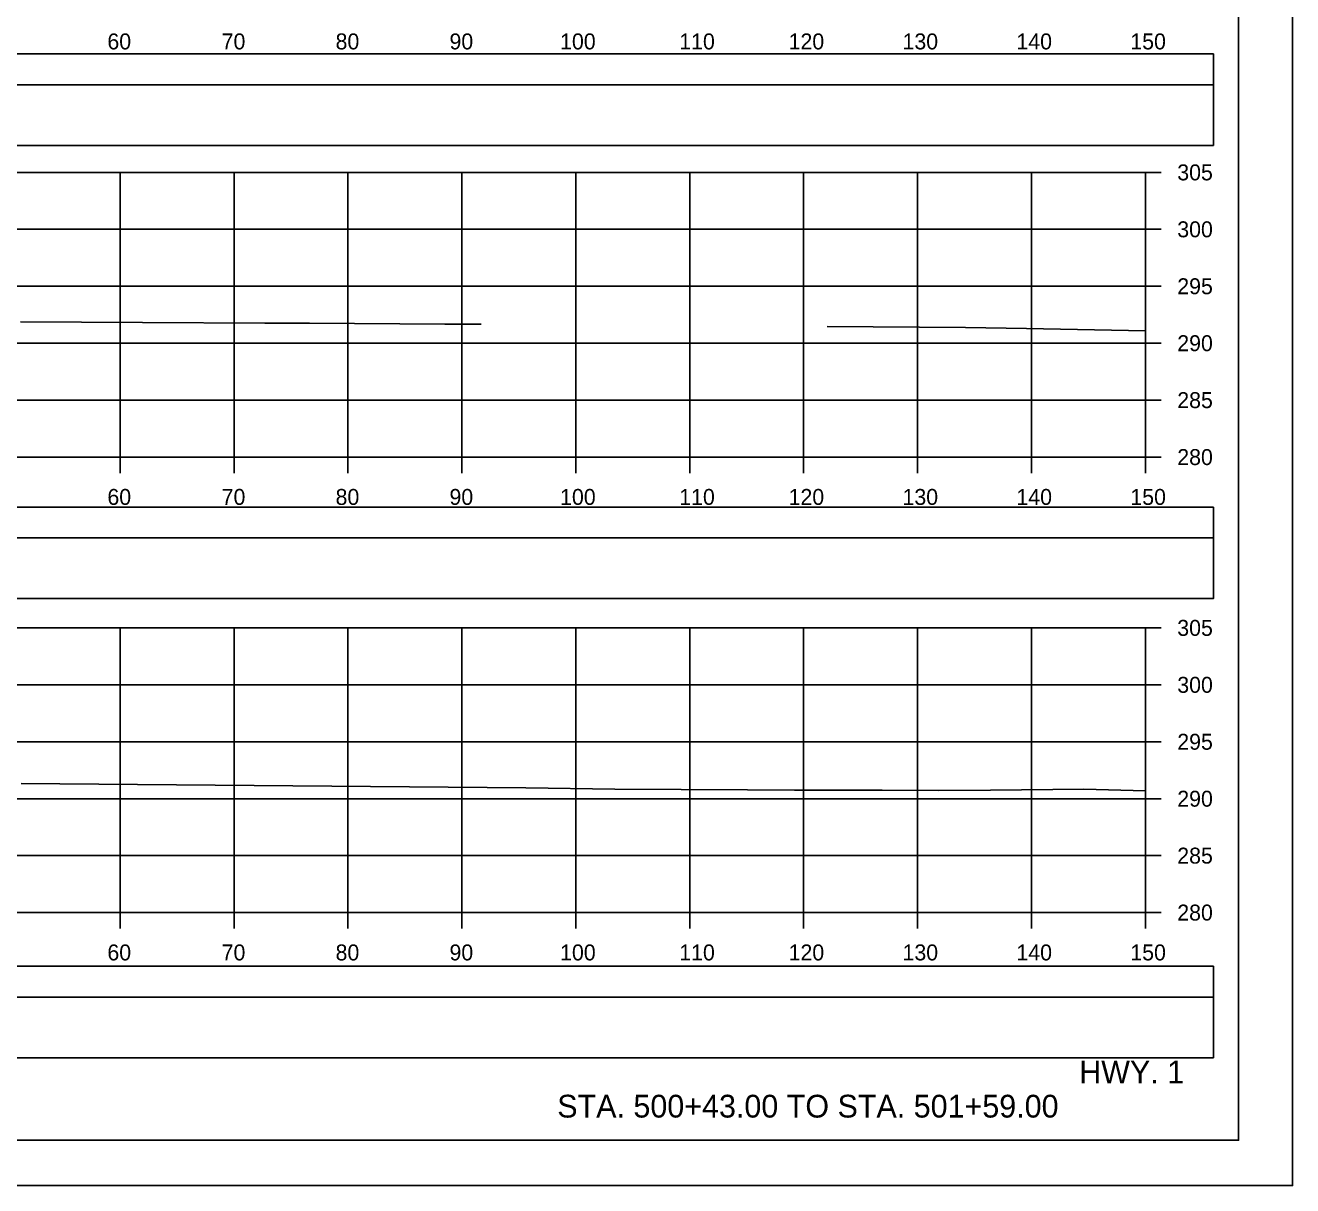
# Model space of a CAD drawing. Extents: x 1370538 to 1372872, y 376220 to 381127.
# Drawn here: x 1372760.3 to 1372871.6, y 376433.8 to 376535.7 of the extents above; entities that cross this region are included whole.
import ezdxf

# ---------------------------------------------------------------- set-up
doc = ezdxf.new("R2010")
doc.units = 0
for name, color, linetype in [('R_Border Notes', 7, 'Continuous'), ('R_Border PE', 7, 'Continuous'), ('R_Border Prem', 7, 'Continuous'), ('R_Dimension', 7, 'Continuous'), ('R_Grid', 7, 'Continuous'), ('R_No Plot', 7, 'Continuous'), ('R_Proposed Road', 7, 'Continuous'), ('T_Detection Zones', 7, 'Continuous')]:
    doc.layers.add(name, color=color, linetype=linetype)

msp = doc.modelspace()

# ---------------------------------------------------------------- linework, layer by layer
at = {"layer": 'R_Border Notes'}
for q in [(1372866.83, 376643.21), (1372550.65, 376437.75)]:
    msp.add_line((1372866.83, 376437.75), q, dxfattribs=at)
at = {"layer": 'R_Border Prem'}
for p, q in [((1372858.65, 376497.75), (1372858.65, 376522.75)), ((1372860.05, 376522.75), (1372858.65, 376522.75)), ((1372860.05, 376517.75), (1372858.65, 376517.75)), ((1372860.05, 376512.75), (1372858.65, 376512.75)), ((1372860.05, 376507.75), (1372858.65, 376507.75)), ((1372860.05, 376502.75), (1372858.65, 376502.75)), ((1372558.65, 376497.75), (1372858.65, 376497.75)), ((1372768.65, 376496.35), (1372768.65, 376497.75)), ((1372778.65, 376496.35), (1372778.65, 376497.75)), ((1372788.65, 376496.35), (1372788.65, 376497.75)), ((1372798.65, 376496.35), (1372798.65, 376497.75)), ((1372808.65, 376496.35), (1372808.65, 376497.75)), ((1372818.65, 376496.35), (1372818.65, 376497.75)), ((1372828.65, 376496.35), (1372828.65, 376497.75)), ((1372838.65, 376496.35), (1372838.65, 376497.75)), ((1372848.65, 376496.35), (1372848.65, 376497.75)), ((1372858.65, 376496.35), (1372858.65, 376497.75)), ((1372860.05, 376497.75), (1372858.65, 376497.75)), ((1372858.65, 376457.75), (1372858.65, 376482.75)), ((1372860.05, 376482.75), (1372858.65, 376482.75)), ((1372860.05, 376477.75), (1372858.65, 376477.75)), ((1372860.05, 376472.75), (1372858.65, 376472.75)), ((1372860.05, 376467.75), (1372858.65, 376467.75)), ((1372860.05, 376462.75), (1372858.65, 376462.75)), ((1372558.65, 376457.75), (1372858.65, 376457.75)), ((1372768.65, 376456.35), (1372768.65, 376457.75)), ((1372778.65, 376456.35), (1372778.65, 376457.75)), ((1372788.65, 376456.35), (1372788.65, 376457.75)), ((1372798.65, 376456.35), (1372798.65, 376457.75)), ((1372808.65, 376456.35), (1372808.65, 376457.75)), ((1372818.65, 376456.35), (1372818.65, 376457.75)), ((1372828.65, 376456.35), (1372828.65, 376457.75)), ((1372838.65, 376456.35), (1372838.65, 376457.75)), ((1372848.65, 376456.35), (1372848.65, 376457.75)), ((1372858.65, 376456.35), (1372858.65, 376457.75)), ((1372860.05, 376457.75), (1372858.65, 376457.75))]:
    msp.add_line(p, q, dxfattribs=at)
at = {"layer": 'R_Dimension'}
for points in [[(1372759.89, 376509.64), (1372770.62, 376509.57), (1372781.34, 376509.51), (1372785.28, 376509.51), (1372797.15, 376509.43), (1372800.34, 376509.43)], [(1372830.72, 376509.21), (1372842.87, 376509.13), (1372848.22, 376509.04), (1372858.65, 376508.85)], [(1372759.96, 376469.09), (1372804.27, 376468.71), (1372812.07, 376468.58), (1372823.71, 376468.53), (1372827.85, 376468.51), (1372835.54, 376468.49), (1372840.52, 376468.48), (1372845.05, 376468.51), (1372853.24, 376468.58), (1372858.65, 376468.45)]]:
    msp.add_lwpolyline(points, dxfattribs=at)
at = {"layer": 'R_Grid'}
for p, q in [((1372558.65, 376522.75), (1372858.65, 376522.75)), ((1372768.65, 376497.75), (1372768.65, 376522.75)), ((1372778.65, 376497.75), (1372778.65, 376522.75)), ((1372788.65, 376497.75), (1372788.65, 376522.75)), ((1372798.65, 376497.75), (1372798.65, 376522.75)), ((1372808.65, 376497.75), (1372808.65, 376522.75)), ((1372818.65, 376497.75), (1372818.65, 376522.75)), ((1372828.65, 376497.75), (1372828.65, 376522.75)), ((1372838.65, 376497.75), (1372838.65, 376522.75)), ((1372848.65, 376497.75), (1372848.65, 376522.75)), ((1372858.65, 376497.75), (1372858.65, 376522.75)), ((1372558.65, 376517.75), (1372858.65, 376517.75)), ((1372558.65, 376512.75), (1372858.65, 376512.75)), ((1372558.65, 376507.75), (1372858.65, 376507.75)), ((1372558.65, 376502.75), (1372858.65, 376502.75)), ((1372558.65, 376497.75), (1372858.65, 376497.75)), ((1372558.65, 376482.75), (1372858.65, 376482.75)), ((1372768.65, 376457.75), (1372768.65, 376482.75)), ((1372778.65, 376457.75), (1372778.65, 376482.75)), ((1372788.65, 376457.75), (1372788.65, 376482.75)), ((1372798.65, 376457.75), (1372798.65, 376482.75)), ((1372808.65, 376457.75), (1372808.65, 376482.75)), ((1372818.65, 376457.75), (1372818.65, 376482.75)), ((1372828.65, 376457.75), (1372828.65, 376482.75)), ((1372838.65, 376457.75), (1372838.65, 376482.75)), ((1372848.65, 376457.75), (1372848.65, 376482.75)), ((1372858.65, 376457.75), (1372858.65, 376482.75)), ((1372558.65, 376477.75), (1372858.65, 376477.75)), ((1372558.65, 376472.75), (1372858.65, 376472.75)), ((1372558.65, 376467.75), (1372858.65, 376467.75)), ((1372558.65, 376462.75), (1372858.65, 376462.75)), ((1372558.65, 376457.75), (1372858.65, 376457.75))]:
    msp.add_line(p, q, dxfattribs=at)
at = {"layer": 'R_No Plot'}
msp.add_line((1372538.25, 376433.77), (1372871.58, 376433.77), dxfattribs=at)
for points in [[(1372538.24, 376647.11), (1372871.58, 376647.11), (1372871.58, 376433.77), (1372538.24, 376433.77)], [(1372784.57, 376643.21), (1372784.57, 376633.33), (1372820.3, 376633.33), (1372820.3, 376630.41), (1372843.5, 376630.41), (1372843.5, 376606.08), (1372866.83, 376606.08), (1372866.83, 376437.75), (1372550.65, 376437.75), (1372550.65, 376643.21)]]:
    msp.add_lwpolyline(points, close=True, dxfattribs=at)
at = {"layer": 'T_Detection Zones'}
for points in [[(1372552.66, 376530.44), (1372864.63, 376530.44), (1372864.63, 376533.15), (1372552.66, 376533.15)], [(1372552.66, 376525.12), (1372864.63, 376525.12), (1372864.63, 376530.44), (1372552.66, 376530.44)], [(1372552.66, 376490.65), (1372864.63, 376490.65), (1372864.63, 376493.35), (1372552.66, 376493.35)], [(1372552.66, 376485.32), (1372864.63, 376485.32), (1372864.63, 376490.65), (1372552.66, 376490.65)], [(1372552.66, 376450.32), (1372864.63, 376450.32), (1372864.63, 376453.03), (1372552.66, 376453.03)], [(1372552.66, 376445), (1372864.63, 376445), (1372864.63, 376450.32), (1372552.66, 376450.32)]]:
    msp.add_lwpolyline(points, close=True, dxfattribs=at)

# ---------------------------------------------------------------- texts
at = {"layer": 'R_Border PE'}
for s, p in [('60', (1372767.53, 376533.55)), ('70', (1372777.56, 376533.55)), ('80', (1372787.56, 376533.55)), ('90', (1372797.56, 376533.55)), ('100', (1372807.27, 376533.55)), ('110', (1372817.73, 376533.55)), ('120', (1372827.33, 376533.55)), ('130', (1372837.33, 376533.55)), ('140', (1372847.33, 376533.55)), ('150', (1372857.33, 376533.55)), ('305', (1372861.45, 376522.05)), ('300', (1372861.45, 376517.05)), ('295', (1372861.45, 376512.05)), ('290', (1372861.45, 376507.05)), ('285', (1372861.45, 376502.05)), ('280', (1372861.45, 376497.05)), ('60', (1372767.53, 376493.55)), ('70', (1372777.56, 376493.55)), ('80', (1372787.56, 376493.55)), ('90', (1372797.56, 376493.55)), ('100', (1372807.27, 376493.55)), ('110', (1372817.73, 376493.55)), ('120', (1372827.33, 376493.55)), ('130', (1372837.33, 376493.55)), ('140', (1372847.33, 376493.55)), ('150', (1372857.33, 376493.55)), ('305', (1372861.45, 376482.05)), ('300', (1372861.45, 376477.05)), ('295', (1372861.45, 376472.05)), ('290', (1372861.45, 376467.05)), ('285', (1372861.45, 376462.05)), ('280', (1372861.45, 376457.05)), ('60', (1372767.53, 376453.55)), ('70', (1372777.56, 376453.55)), ('80', (1372787.56, 376453.55)), ('90', (1372797.56, 376453.55)), ('100', (1372807.27, 376453.55)), ('110', (1372817.73, 376453.55)), ('120', (1372827.33, 376453.55)), ('130', (1372837.33, 376453.55)), ('140', (1372847.33, 376453.55)), ('150', (1372857.33, 376453.55))]:
    msp.add_text(s, height=1.4, dxfattribs=at).set_placement(p)
at = {"layer": 'R_Proposed Road'}
for s, p in [('HWY. 1', (1372852.84, 376442.75)), ('STA. 500+43.00 TO STA. 501+59.00', (1372807.02, 376439.75))]:
    msp.add_text(s, height=2, dxfattribs=at).set_placement(p)

doc.saveas('drawing.dxf')
